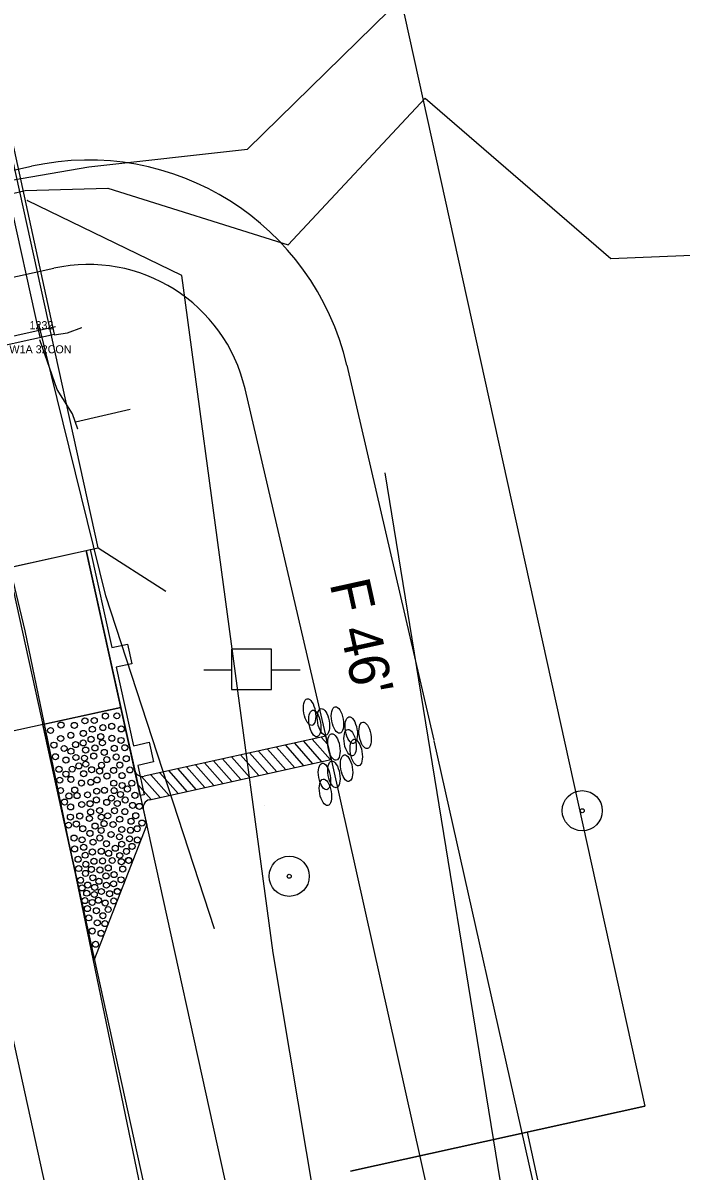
# Model space of a CAD drawing. Extents: x 2519952 to 2531965, y 848341 to 887632.
# Drawn here: x 2524514.7 to 2524596.6, y 869788.7 to 869931.6 of the extents above; entities that cross this region are included whole.
import ezdxf

# ---------------------------------------------------------------- set-up
doc = ezdxf.new("R2010")
doc.units = 0
for name, color, linetype in [('RD_EV_JW', 7, 'Continuous'), ('RD_EX_BldgApp', 7, 'Continuous'), ('RD_EX_BldgApp_txCode', 7, 'Continuous'), ('RD_EX_Bridge', 7, 'Continuous'), ('RD_EX_Conc', 7, 'Continuous'), ('RD_EX_DR_Pipe', 7, 'Continuous'), ('RD_EX_DV_Prop', 7, 'Continuous'), ('RD_EX_DV_PropPin', 7, 'Continuous'), ('RD_EX_GuardRail', 7, 'Continuous'), ('RD_EX_H2O', 7, 'Continuous'), ('RD_EX_Misc', 7, 'Continuous'), ('RD_EX_Road', 7, 'Continuous'), ('RD_EX_RW', 7, 'Continuous'), ('RD_EX_UT', 7, 'Continuous'), ('RD_EX_VEG', 7, 'Continuous'), ('RD_HC_Cl', 7, 'Continuous'), ('RD_PD_Bridge', 7, 'Continuous'), ('RD_PD_CstnLmt', 7, 'Continuous'), ('RD_PD_DR_ErosCtrl', 7, 'Continuous'), ('RD_PD_Final_TrvlWay', 7, 'Continuous'), ('RD_PD_GR', 7, 'Continuous'), ('RD_PD_PaveShd', 7, 'Continuous'), ('RD_PD_RW', 7, 'Continuous'), ('RD_PD_TX_CstnLmt', 7, 'Continuous'), ('RD_SMD_Locator', 7, 'Continuous')]:
    doc.layers.add(name, color=color, linetype=linetype)

# ---------------------------------------------------------------- blocks, each defined once
blk = doc.blocks.new('TBC1')
at = {"layer": 'RD_PD_GR'}
blk.add_lwpolyline([(12.5, 2.5), (15, 2.5), (15, 0.49), (25, 0.49), (25, 2.5), (27.5, 2.5), (27.5, 0.49), (31.25, 0.49), (31.25, 0), (0, 0), (0, 0.49), (12.5, 0.49)], close=True, dxfattribs=at)

msp = doc.modelspace()

# ---------------------------------------------------------------- linework, layer by layer
at = {"layer": 'RD_EV_JW'}
msp.add_lwpolyline([(2524642.32, 869355.11), (2524607.87, 869514.61), (2524585.46, 869620.06), (2524561.39, 869723.4), (2524545.88, 869815.87), (2524534.52, 869900.16), (2524515.28, 869909.5)], dxfattribs=at)
at = {"layer": 'RD_EX_BldgApp'}
msp.add_lwpolyline([(2524516.89, 869892.47), (2524508.77, 869928.99), (2524500.76, 869966.53)], dxfattribs=at)
at = {"layer": 'RD_EX_Bridge'}
for points in [[(2524472.36, 869882.63), (2524518.65, 869892.86), (2524502.52, 869966.92), (2524455.6, 869956.47), (2524472.36, 869882.63)], [(2524518.6, 869892.76), (2524520.29, 869893.03), (2524522.05, 869893.68)]]:
    msp.add_lwpolyline(points, dxfattribs=at)
at = {"layer": 'RD_EX_Conc'}
msp.add_lwpolyline([(2524521.57, 869881.04), (2524520.91, 869882.92), (2524518.99, 869885.98), (2524516.82, 869892.13)], dxfattribs=at)
at = {"layer": 'RD_EX_DR_Pipe'}
msp.add_line((2524521.29, 869881.95), (2524528.08, 869883.52), dxfattribs=at)
at = {"layer": 'RD_EX_DV_Prop'}
for p, q in [((2524527.61, 870089.75), (2524592.12, 869796.77)), ((2524592.12, 869796.77), (2524555.5, 869788.71))]:
    msp.add_line(p, q, dxfattribs=at)
at = {"layer": 'RD_EX_DV_PropPin'}
for centre, radius in [((2524584.34, 869833.55), 2.5), ((2524584.34, 869833.55), 0.25), ((2524547.87, 869825.39), 2.5), ((2524547.87, 869825.39), 0.25)]:
    msp.add_circle(centre, radius, dxfattribs=at)
at = {"layer": 'RD_EX_GuardRail'}
msp.add_lwpolyline([(2524538.57, 869818.84), (2524525.06, 869860.29), (2524516.73, 869894.11)], dxfattribs=at)
at = {"layer": 'RD_EX_H2O'}
for points in [[(2524280.27, 869571.37), (2524295.57, 869662.01), (2524325.04, 869706.78), (2524321.22, 869733.31), (2524284.03, 869760.46), (2524298.4, 869779.15), (2524330.51, 869802.71), (2524376.62, 869842.08), (2524442.17, 869881.92), (2524466.83, 869904.02), (2524522.92, 869913.69), (2524522.92, 869913.69), (2524542.69, 869915.86), (2524587.71, 869959.96)], [(2524525.28, 869911.03), (2524547.76, 869903.95), (2524564.78, 869922.22), (2524587.89, 869902.27), (2524625.25, 869903.81), (2524663.81, 869914.53), (2524675.63, 869888.4)], [(2524490.19, 869746.15), (2524461.13, 869856.58), (2524453.72, 869867.75), (2524467.93, 869899.58), (2524515.02, 869910.74), (2524525.28, 869911.03)]]:
    msp.add_lwpolyline(points, dxfattribs=at)
at = {"layer": 'RD_EX_Misc'}
msp.add_line((2524471.88, 869883.34), (2524518.8, 869893.81), dxfattribs=at)
at = {"layer": 'RD_EX_Road'}
for p, q in [((2524515.03, 869855.95), (2524506.83, 869889.91)), ((2524535.42, 869757.49), (2524515.03, 869855.95))]:
    msp.add_line(p, q, dxfattribs=at)
at = {"layer": 'RD_EX_RW'}
for p in [(2524527.61, 870089.75), (2524555.5, 869788.7)]:
    msp.add_line(p, (2524592.12, 869796.77), dxfattribs=at)
at = {"layer": 'RD_EX_UT'}
for p, q in [((2524545.68, 869853.65), (2524540.68, 869853.65)), ((2524540.68, 869853.65), (2524540.68, 869848.65)), ((2524545.68, 869848.65), (2524545.68, 869853.65)), ((2524537.25, 869851.09), (2524540.72, 869851.09)), ((2524545.61, 869851.09), (2524549.25, 869851.09)), ((2524540.68, 869848.65), (2524545.68, 869848.65))]:
    msp.add_line(p, q, dxfattribs=at)
at = {"layer": 'RD_EX_VEG'}
msp.add_lwpolyline([(2524696.2, 869380.99), (2524663.62, 869364.09), (2524622.38, 869576.48), (2524577.79, 869765.19), (2524559.81, 869875.59)], dxfattribs=at)
at = {"layer": 'RD_HC_Cl'}
msp.add_line((2524338.62, 870599.23), (2524895.21, 868071.59), dxfattribs=at)
at = {"layer": 'RD_PD_Bridge'}
for p, q in [((2524478.18, 869856.16), (2524524.08, 869866.26)), ((2524522.62, 869865.94), (2524526.92, 869846.41)), ((2524524.08, 869866.26), (2524532.51, 869860.88)), ((2524526.92, 869846.41), (2524483.95, 869836.95))]:
    msp.add_line(p, q, dxfattribs=at)
for points in [[(2524524.08, 869866.26), (2524496.13, 869993.22)], [(2524478.18, 869856.16), (2524524.08, 869866.26)]]:
    msp.add_lwpolyline(points, dxfattribs=at)
at = {"layer": 'RD_PD_CstnLmt'}
for p, q in [((2524542.37, 869886.05), (2524553.2, 869839.4)), ((2524553.2, 869839.4), (2524575.06, 869741.81))]:
    msp.add_line(p, q, dxfattribs=at)
msp.add_lwpolyline([(2524468.05, 869889.93), (2524518.59, 869901.05)], dxfattribs=at)
msp.add_arc((2524522.89, 869881.52), 20, 13.0724, 102.4185, dxfattribs=at)
at = {"layer": 'RD_PD_DR_ErosCtrl'}
for p, q in [((2524555.04, 869888.99), (2524565.87, 869842.34)), ((2524565.89, 869842.24), (2524587.75, 869744.65))]:
    msp.add_line(p, q, dxfattribs=at)
msp.add_lwpolyline([(2524465.25, 869902.62), (2524515.79, 869913.75)], dxfattribs=at)
msp.add_arc((2524522.89, 869881.52), 33, 13.0724, 102.4185, dxfattribs=at)
at = {"layer": 'RD_PD_Final_TrvlWay'}
msp.add_line((2524439.2, 870198.28), (2524713.39, 868953.11), dxfattribs=at)
at = {"layer": 'RD_PD_GR'}
msp.add_line((2524529.34, 869835.42), (2524687.94, 869115.18), dxfattribs=at)
at = {"layer": 'RD_PD_PaveShd'}
for p, q in [((2524517.15, 869844.26), (2524526.92, 869846.41)), ((2524526.92, 869846.41), (2524528.86, 869837.62)), ((2524517.15, 869844.26), (2524523.61, 869814.96)), ((2524552.41, 869842.82), (2524529.83, 869837.84)), ((2524549.64, 869842.21), (2524551.91, 869839.64)), ((2524549.64, 869842.21), (2524551.91, 869839.64)), ((2524550.75, 869842.45), (2524553.03, 869839.88)), ((2524550.75, 869842.45), (2524553.03, 869839.88)), ((2524551.87, 869842.7), (2524552.64, 869841.83)), ((2524553.09, 869839.9), (2524552.41, 869842.82)), ((2524542.93, 869840.73), (2524545.21, 869838.16)), ((2524542.93, 869840.73), (2524545.21, 869838.16)), ((2524544.05, 869840.97), (2524546.04, 869838.72)), ((2524544.05, 869840.97), (2524546.32, 869838.4)), ((2524545.17, 869841.22), (2524547.44, 869838.65)), ((2524545.17, 869841.22), (2524547.44, 869838.65)), ((2524546.28, 869841.47), (2524548.56, 869838.9)), ((2524546.28, 869841.47), (2524548.56, 869838.9)), ((2524547.4, 869841.71), (2524549.67, 869839.14)), ((2524547.4, 869841.71), (2524549.67, 869839.14)), ((2524548.52, 869841.96), (2524550.79, 869839.39)), ((2524548.52, 869841.96), (2524550.79, 869839.39)), ((2524530.48, 869834.91), (2524553.09, 869839.9)), ((2524536.23, 869839.25), (2524538.5, 869836.68)), ((2524536.23, 869839.25), (2524538.5, 869836.68)), ((2524537.35, 869839.5), (2524539.62, 869836.93)), ((2524537.35, 869839.5), (2524539.62, 869836.93)), ((2524538.46, 869839.74), (2524540.74, 869837.17)), ((2524538.46, 869839.74), (2524540.74, 869837.17)), ((2524539.58, 869839.99), (2524541.86, 869837.42)), ((2524539.58, 869839.99), (2524541.86, 869837.42)), ((2524540.7, 869840.24), (2524542.97, 869837.66)), ((2524540.7, 869840.24), (2524542.97, 869837.66)), ((2524541.82, 869840.48), (2524544.09, 869837.91)), ((2524541.82, 869840.48), (2524544.09, 869837.91)), ((2524529.48, 869837.82), (2524531.8, 869835.2)), ((2524530.65, 869838.02), (2524532.92, 869835.45)), ((2524530.65, 869838.02), (2524532.92, 869835.45)), ((2524531.76, 869838.26), (2524534.04, 869835.69)), ((2524531.76, 869838.26), (2524534.04, 869835.69)), ((2524532.88, 869838.51), (2524535.15, 869835.94)), ((2524532.88, 869838.51), (2524535.15, 869835.94)), ((2524534, 869838.76), (2524536.27, 869836.19)), ((2524535.11, 869839), (2524537.39, 869836.43)), ((2524535.11, 869839), (2524537.39, 869836.43)), ((2524528.86, 869837.62), (2524529.5, 869834.69)), ((2524529.03, 869836.82), (2524530.69, 869834.95)), ((2524529.5, 869834.69), (2524530.15, 869831.76)), ((2524523.61, 869814.96), (2524530.15, 869831.76))]:
    msp.add_line(p, q, dxfattribs=at)
for centre in [(2524522.45, 869844.73), (2524522.45, 869844.73), (2524523.61, 869844.77), (2524523.61, 869844.77), (2524524.99, 869845.33), (2524524.99, 869845.33), (2524526.42, 869845.35), (2524526.42, 869845.35), (2524526.42, 869845.35), (2524518.17, 869843.53), (2524518.17, 869843.53), (2524519.47, 869844.21), (2524519.47, 869844.21), (2524521.13, 869844.16), (2524521.13, 869844.16), (2524522.25, 869843.17), (2524522.25, 869843.17), (2524523.37, 869843.69), (2524523.37, 869843.69), (2524524.68, 869843.89), (2524524.68, 869843.89), (2524525.78, 869844.05), (2524525.78, 869844.05), (2524526.97, 869843.72), (2524526.97, 869843.72), (2524518.59, 869841.71), (2524518.59, 869841.71), (2524519.43, 869842.53), (2524519.43, 869842.53), (2524520.69, 869842.93), (2524520.69, 869842.93), (2524521.29, 869841.77), (2524521.29, 869841.77), (2524522.23, 869841.98), (2524522.23, 869841.98), (2524523.21, 869842.44), (2524523.21, 869842.44), (2524524.42, 869842.77), (2524524.42, 869842.77), (2524524.62, 869841.99), (2524524.62, 869841.99), (2524525.8, 869842.56), (2524525.8, 869842.56), (2524526.94, 869842.29), (2524526.94, 869842.29), (2524519.86, 869841.29), (2524519.86, 869841.29), (2524520.71, 869840.95), (2524520.71, 869840.95), (2524522.54, 869841.1), (2524522.54, 869841.1), (2524523.54, 869840.35), (2524523.54, 869840.35), (2524523.69, 869841.36), (2524523.69, 869841.36), (2524524.86, 869840.8), (2524524.86, 869840.8), (2524526.1, 869841.32), (2524526.1, 869841.32), (2524527.41, 869841.39), (2524527.41, 869841.39), (2524518.78, 869840.27), (2524518.78, 869840.27), (2524520.08, 869839.85), (2524520.08, 869839.85), (2524521.33, 869840.17), (2524521.33, 869840.17), (2524521.69, 869839.12), (2524521.69, 869839.12), (2524522.39, 869840.09), (2524522.56, 869839.34), (2524522.56, 869839.34), (2524524.51, 869839.2), (2524524.51, 869839.2), (2524525.17, 869839.91), (2524525.17, 869839.91), (2524526.34, 869840.23), (2524526.34, 869840.23), (2524526.79, 869839.23), (2524526.79, 869839.23), (2524527.59, 869840.02), (2524527.59, 869840.02), (2524519.22, 869838.7), (2524519.22, 869838.7), (2524520.09, 869838.1), (2524520.09, 869838.1), (2524520.7, 869837.44), (2524520.7, 869837.44), (2524520.86, 869838.72), (2524520.86, 869838.72), (2524522.29, 869838.15), (2524522.29, 869838.15), (2524523.28, 869838.65), (2524523.28, 869838.65), (2524524.27, 869838.48), (2524524.27, 869838.48), (2524525.19, 869837.86), (2524525.19, 869837.86), (2524526.02, 869838.57), (2524526.02, 869838.57), (2524527.07, 869837.92), (2524527.07, 869837.92), (2524528.04, 869838.62), (2524528.04, 869838.62), (2524519.32, 869837.35), (2524519.32, 869837.35), (2524519.41, 869836.06), (2524519.41, 869836.06), (2524521.18, 869836.12), (2524521.18, 869836.12), (2524522.02, 869836.99), (2524522.02, 869836.99), (2524523.18, 869837.09), (2524523.18, 869837.09), (2524523.95, 869837.38), (2524523.95, 869837.38), (2524524.88, 869836.09), (2524524.88, 869836.09), (2524526.03, 869836.97), (2524526.03, 869836.97), (2524526.08, 869836.05), (2524526.08, 869836.05), (2524527.08, 869836.69), (2524527.08, 869836.69), (2524527.73, 869836.25), (2524527.73, 869836.25), (2524528.28, 869836.97), (2524528.28, 869836.97), (2524519.91, 869834.62), (2524520.46, 869835.38), (2524520.46, 869835.38), (2524521.47, 869835.43), (2524521.47, 869835.43), (2524522.77, 869835.52), (2524522.77, 869835.52), (2524523.88, 869834.89), (2524523.88, 869834.89), (2524523.92, 869835.98), (2524523.92, 869835.98), (2524525.16, 869834.58), (2524525.16, 869834.58), (2524525.75, 869835.11), (2524525.75, 869835.11), (2524526.87, 869835.57), (2524526.87, 869835.57), (2524527.46, 869834.88), (2524527.46, 869834.88), (2524528.67, 869835.46), (2524528.67, 869835.46), (2524520.66, 869834.02), (2524520.66, 869834.02), (2524522.05, 869834.32), (2524522.05, 869834.32), (2524523.09, 869834.42), (2524523.09, 869834.42), (2524523.15, 869833.39), (2524523.15, 869833.39), (2524524.28, 869833.57), (2524524.28, 869833.57), (2524526.13, 869833.54), (2524526.13, 869833.54), (2524526.47, 869834.44), (2524526.47, 869834.44), (2524527.42, 869833.43), (2524527.42, 869833.43), (2524528.37, 869834.21), (2524528.37, 869834.21), (2524529.22, 869834.09), (2524529.22, 869834.09), (2524520.41, 869831.75), (2524520.41, 869831.75), (2524520.64, 869832.75), (2524520.64, 869832.75), (2524521.38, 869831.89), (2524521.38, 869831.89), (2524521.8, 869832.88), (2524521.8, 869832.88), (2524523.01, 869832.58), (2524523.01, 869832.58), (2524524.48, 869832.74), (2524524.48, 869832.74), (2524524.83, 869831.94), (2524524.83, 869831.94), (2524525.29, 869832.91), (2524525.29, 869832.91), (2524525.95, 869831.83), (2524525.95, 869831.83), (2524526.77, 869832.49), (2524526.77, 869832.49), (2524528.19, 869832.23), (2524528.19, 869832.23), (2524528.77, 869832.92), (2524528.77, 869832.92), (2524529.55, 869832.01), (2524529.55, 869832.01), (2524529.55, 869832.01), (2524522.18, 869831.31), (2524522.18, 869831.31), (2524523.07, 869830.72), (2524523.07, 869830.72), (2524523.71, 869831.64), (2524523.71, 869831.64), (2524524.47, 869831.09), (2524524.47, 869831.09), (2524525.7, 869830.59), (2524525.7, 869830.59), (2524526.75, 869830.3), (2524526.75, 869830.3), (2524527.03, 869831.21), (2524527.03, 869831.21), (2524528.12, 869831.11), (2524528.12, 869831.11), (2524528.95, 869831.31), (2524528.95, 869831.31), (2524521.1, 869830.14), (2524521.1, 869830.14), (2524522.09, 869829.92), (2524522.09, 869829.92), (2524522.29, 869829), (2524522.29, 869829), (2524523.46, 869829.63), (2524523.46, 869829.63), (2524524.3, 869830.15), (2524524.3, 869830.15), (2524525.13, 869829.44), (2524525.13, 869829.44), (2524526.22, 869828.87), (2524526.22, 869828.87), (2524527.03, 869829.38), (2524527.03, 869829.38), (2524528, 869830.05), (2524528, 869830.05), (2524528.31, 869829.11), (2524528.31, 869829.11), (2524528.98, 869829.91), (2524528.98, 869829.91), (2524521.16, 869828.79), (2524521.16, 869828.79), (2524521.59, 869827.5), (2524521.59, 869827.5), (2524522.48, 869828.01), (2524522.48, 869828.01), (2524523.37, 869828.41), (2524523.37, 869828.41), (2524524.48, 869828.5), (2524524.48, 869828.5), (2524525.39, 869828.25), (2524525.39, 869828.25), (2524526.78, 869827.97), (2524526.78, 869827.97), (2524527.62, 869828.48), (2524527.62, 869828.48), (2524521.67, 869826.35), (2524521.67, 869826.35), (2524522.56, 869826.88), (2524522.56, 869826.88), (2524523.25, 869826.25), (2524523.25, 869826.25), (2524523.57, 869827.25), (2524523.57, 869827.25), (2524524.32, 869826.17), (2524524.32, 869826.17), (2524524.64, 869827.3), (2524524.64, 869827.3), (2524525.35, 869826.43), (2524525.35, 869826.43), (2524525.84, 869827.35), (2524525.84, 869827.35), (2524526.98, 869827.2), (2524526.98, 869827.2), (2524527.15, 869826.29), (2524527.15, 869826.29), (2524527.89, 869827.35), (2524527.9, 869827.36), (2524521.9, 869824.89), (2524521.9, 869824.89), (2524522.52, 869825.75), (2524522.52, 869825.75), (2524523.43, 869825.2), (2524523.43, 869825.2), (2524524.19, 869824.77), (2524524.19, 869824.77), (2524525.07, 869825.43), (2524525.07, 869825.43), (2524526.07, 869825.6), (2524526.07, 869825.6), (2524526.94, 869824.95), (2524526.94, 869824.95), (2524522.09, 869823.94), (2524522.09, 869823.94), (2524522.67, 869823.28), (2524522.67, 869823.28), (2524522.8, 869824.29), (2524522.8, 869824.29), (2524523.66, 869824), (2524523.66, 869824), (2524524.5, 869823.49), (2524524.5, 869823.49), (2524525.12, 869824.28), (2524525.12, 869824.28), (2524525.52, 869823.21), (2524525.52, 869823.21), (2524526.02, 869824.45), (2524526.02, 869824.45), (2524526.48, 869823.49), (2524526.49, 869823.52), (2524522.44, 869822.36), (2524522.44, 869822.36), (2524523.35, 869822.13), (2524523.35, 869822.13), (2524523.61, 869823.12), (2524523.61, 869823.12), (2524524.12, 869822.4), (2524524.12, 869822.4), (2524524.97, 869822.05), (2524524.97, 869822.05), (2524526.04, 869822.32), (2524526.04, 869822.32), (2524522.75, 869821.36), (2524522.75, 869821.36), (2524523.88, 869821.1), (2524523.88, 869821.1), (2524524.68, 869820.48), (2524524.68, 869820.48), (2524525.34, 869821.25), (2524522.93, 869820.21), (2524522.93, 869820.21), (2524523.98, 869819.59), (2524523.98, 869819.59), (2524524.93, 869819.5), (2524524.93, 869819.5), (2524523.35, 869818.57), (2524523.35, 869818.57), (2524524.45, 869818.29), (2524524.45, 869818.29), (2524523.77, 869816.92)]:
    msp.add_circle(centre, 0.375, dxfattribs=at)
for centre, start, end in [((2524529.62, 869838.81), 192.4185, 282.4481), ((2524530.69, 869833.93), 102.4481, 192.4185)]:
    msp.add_arc(centre, 1, start, end, dxfattribs=at)
for centre in [(2524550.41, 869845.82), (2524550.41, 869845.82), (2524553.88, 869844.83), (2524553.88, 869844.83), (2524551.06, 869844.4), (2524551.06, 869844.4), (2524552.13, 869844.6), (2524552.13, 869844.6), (2524555.6, 869843.57), (2524555.6, 869843.57), (2524555.45, 869842.01), (2524555.45, 869842.01), (2524557.31, 869842.93), (2524557.31, 869842.93), (2524553.44, 869841.48), (2524553.44, 869841.48), (2524556.22, 869840.78), (2524556.22, 869840.78), (2524552.26, 869837.81), (2524553.44, 869838.06), (2524553.44, 869838.06), (2524555.01, 869838.84), (2524555.01, 869838.84), (2524552.38, 869835.83)]:
    msp.add_ellipse(centre, major_axis=(0.29, -1.65), ratio=0.429445, dxfattribs=at)
at = {"layer": 'RD_PD_RW'}
msp.add_line((2524577.47, 869793.54), (2524685, 869305.24), dxfattribs=at)
at = {"layer": 'RD_SMD_Locator'}
for centre in [(2524564.78, 869922.22), (2524542.69, 869915.86), (2524522.92, 869913.69), (2524522.92, 869913.69), (2524515.02, 869910.74), (2524525.28, 869911.03), (2524525.28, 869911.03), (2524515.28, 869909.5), (2524547.76, 869903.95), (2524587.89, 869902.27), (2524534.52, 869900.16), (2524516.73, 869894.11), (2524518.8, 869893.81), (2524522.05, 869893.68), (2524516.82, 869892.13), (2524516.89, 869892.47), (2524518.6, 869892.76), (2524518.65, 869892.86), (2524520.29, 869893.03), (2524518.99, 869885.98), (2524528.08, 869883.52), (2524520.91, 869882.92), (2524521.29, 869881.95), (2524521.57, 869881.04), (2524559.81, 869875.59), (2524525.06, 869860.29), (2524515.03, 869855.95), (2524544.85, 869834.25), (2524538.57, 869818.84), (2524545.88, 869815.87)]:
    msp.add_circle(centre, 0.001, dxfattribs=at)

# ---------------------------------------------------------------- block references
at = {"layer": 'RD_PD_Bridge', "rotation": -77.58151740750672}
msp.add_blockref('TBC1', (2524522.62, 869865.94), dxfattribs=at)

# ---------------------------------------------------------------- texts
at = {"layer": 'RD_EX_BldgApp_txCode'}
for s, p in [('1232', (2524515.55, 869893.47)), ('W1A 32CON', (2524513.05, 869890.47))]:
    msp.add_text(s, height=1, dxfattribs=at).set_placement(p)
at = {"layer": 'RD_PD_TX_CstnLmt'}
msp.add_text("F 46'", height=5, rotation=282.4185, dxfattribs=at).set_placement((2524552.89, 869861.83))

doc.saveas('drawing.dxf')
